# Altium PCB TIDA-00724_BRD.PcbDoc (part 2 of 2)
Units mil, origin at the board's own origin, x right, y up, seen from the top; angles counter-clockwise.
Board outline 4500 x 3350 mil, 4 copper layers (Top Layer, Signal Layer 1, Signal Layer 2, Bottom Layer), stack 61.634 mil thick; 147 components, 76 nets, 383 pads, 213 vias.
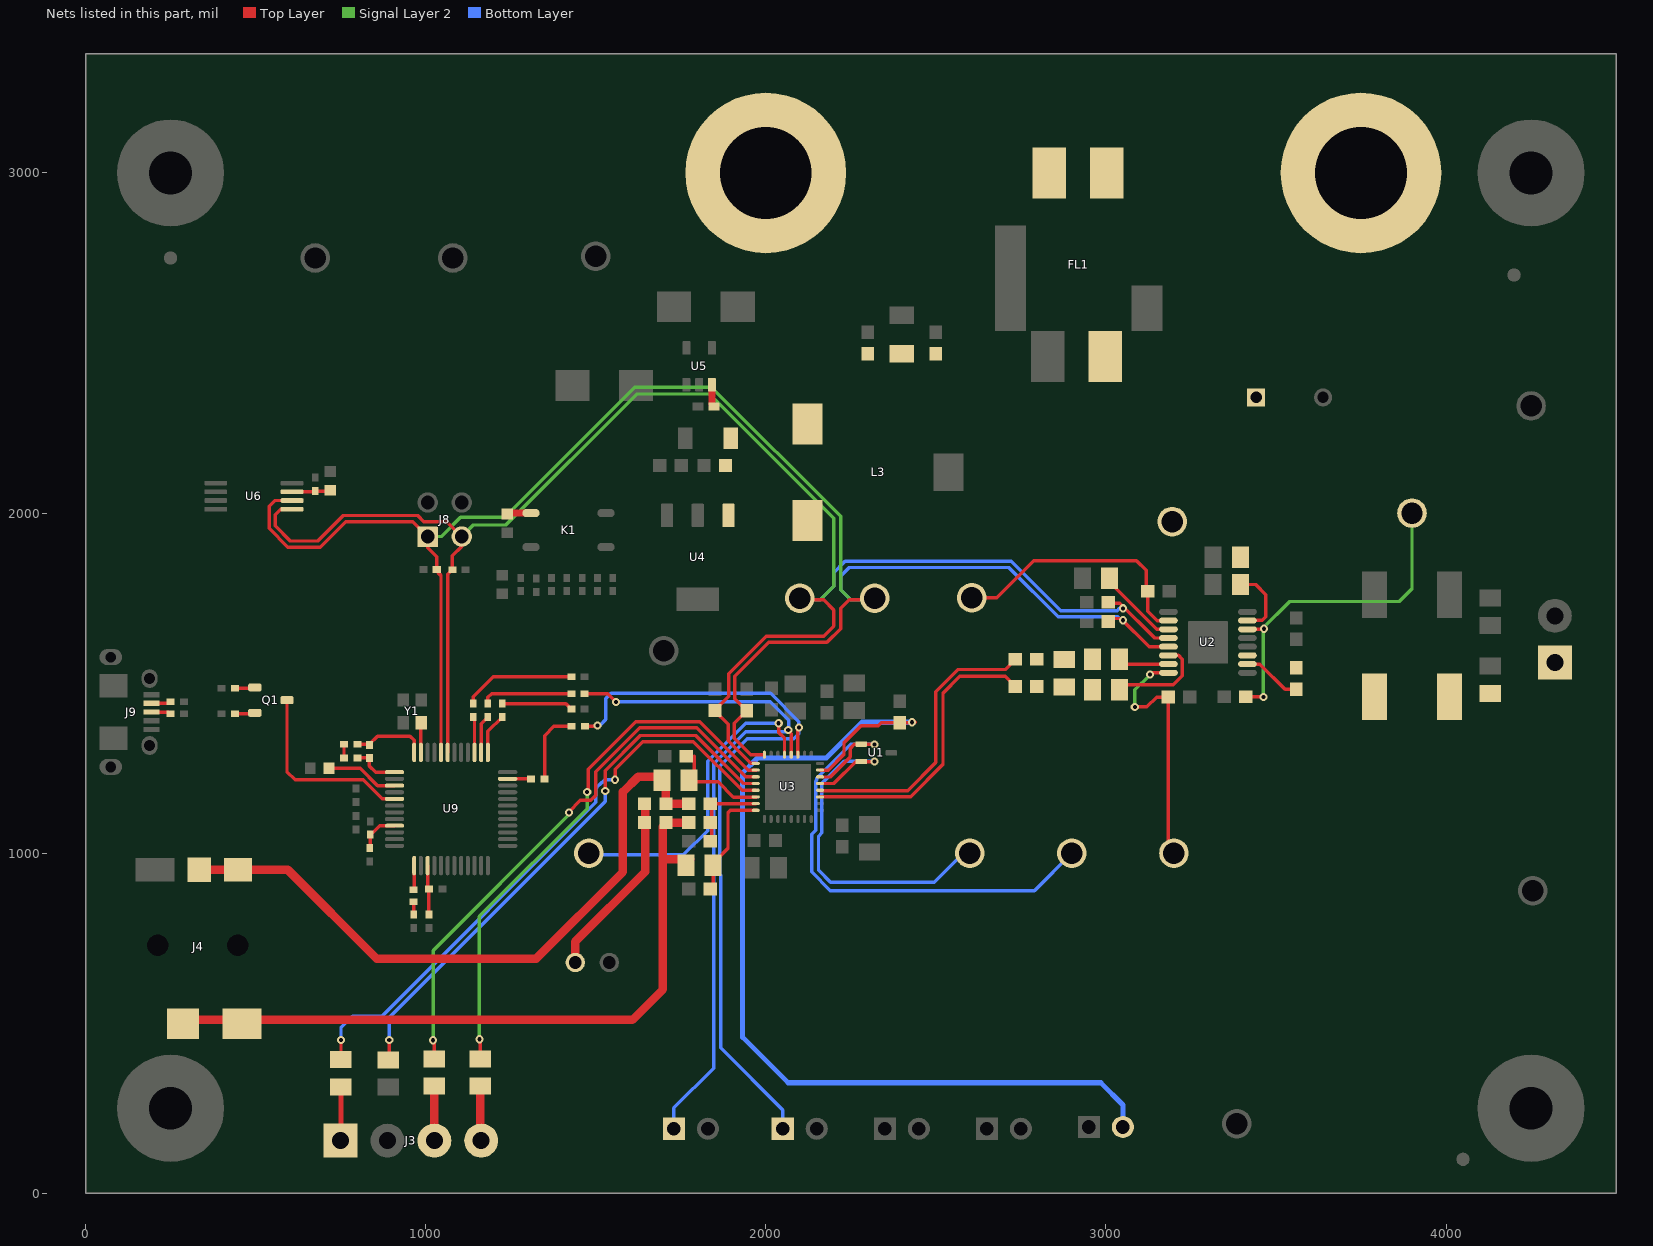
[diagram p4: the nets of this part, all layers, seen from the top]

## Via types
v1: diameter 24, hole 12, Top Layer to Bottom Layer, tented both sides, 188 vias
v2: diameter 15.75, hole 7.87, Top Layer to Bottom Layer, tented both sides, 18 vias
v3: diameter 19.68, hole 7.87, Top Layer to Bottom Layer, 5 vias
v4: diameter 20, hole 10, Top Layer to Bottom Layer, tented both sides, 2 vias

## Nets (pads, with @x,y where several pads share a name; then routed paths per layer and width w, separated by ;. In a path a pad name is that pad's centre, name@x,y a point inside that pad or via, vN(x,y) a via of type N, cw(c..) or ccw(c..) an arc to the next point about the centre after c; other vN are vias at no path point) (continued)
NetC6_2: C6.2 U3.12 | length 1664.3
  Top Layer w10: C6.2@890,383.5 893,386.5 v1(893,451) ; v1@1528,1186 1528,1242.72 1631.28,1346 1794.72,1346 1935.88,1204.84 U3.12@1970.51,1204.84
  Bottom Layer w10: v1(893,451) 893,517 1528,1152 v1(1528,1183)
NetC7_1: C7.1 J3.1 | length 166.9
  Top Layer w15: J3.1@750,155 751,156 C7.1@751,321.5
NetC7_2: C7.2 U3.13 | length 1771.4
  Top Layer w10: C7.2@751,384.5 v1(751,451) ; v1(1557,1216) 1557,1246.44 1638.68,1328.13 1787.32,1328.13 1930.29,1185.16 U3.13@1970.51,1185.16
  Bottom Layer w10: v1(751,451) 751,487 785,521 871.72,521 1500,1149.28 1500,1189 1503.13,1192.13 1503.13,1193.3 1517.7,1207.87 1518.87,1207.87 1527,1216 v1(1557,1216)
NetC8_1: C8.1 C9.2 R6.1
NetC8_2: C8.2 C12.2 R10.1
NetC9_1: C9.1 U2.6 | length 293.6
  Top Layer w10: C9.1@3040,1485 3050,1495 3197.86,1495 3224.29,1521.43 3224.29,1570.71 3213.39,1581.61 U2.6@3183.86,1581.61
NetC10_1: C10.1 L2.1 U2.11
NetC10_2: C10.2 U2.10 | length 174.3
  Top Layer w10: U2.10@3416.14,1556.02 3452.98,1556.02 3526.5,1482.5 C10.2@3560,1482.5
NetC11_1: C11.1 J1.1 L2.2
NetC12_1: C12.1 U2.7 | length 135.8
  Top Layer w10: C12.1@3048.02,1556.02 U2.7@3183.86,1556.02
NetC13_1: C13.1 U2.3 | length 243.7
  Top Layer w10: C13.1@3010,1810 3010,1798 3149.61,1658.39 U2.3@3183.86,1658.39
NetC24_1: C24.1 J3.4 | length 162.2
  Top Layer w25: C24.1@1160.59,314.41 C24.1@1160,315 1160,158.39 J3.4@1163.39,155
NetC24_2: C24.2 U3.10 | length 1600.1
  Top Layer w10: v1(1158,453) 1160,451 C24.2@1160,395 ; v1(1475,1180) 1478,1180 1478,1247 1618,1387 1806,1387 1949,1244 U3.10@1971.77,1244
  Signal Layer 2 w10: v1@1158,451 v1(1158,453) 1158,814 1475,1131 v1@1475,1178 ; v1(1475,1180) v1@1477,1180
NetC25_1: C25.1 J3.3 | length 163.4
  Top Layer w25: C25.1@1022.8,312.8 C25.1@1025,315 1025,155.59 J3.3@1025.59,155
NetC25_2: C25.2 U3.11 | length 1647.8
  Top Layer w10: v1(1022,450) 1025,447 C25.2@1025,395 ; v1(1421,1120) 1421,1121 1455.13,1155.13 1485.3,1155.13 1499.87,1169.7 1499.87,1169.87 1500,1170 1500,1240 1629,1369 1797,1369 1941,1225 U3.11@1971.77,1225
  Signal Layer 2 w10: v1@1020,449 v1@1020,450 ; v1(1022,450) 1022,714 1421,1113 v1(1421,1120)
NetC26_1: C26.1 C27.2 U3.14 | length 275.9
  Top Layer w10: 1789.5,1285 1789.5,1210 1860,1210 1905,1165 U3.14@1971.77,1165
NetC27_1: C27.1 J4.3 J4.5 R14.1 R16.2 | length 1974.5
  Top Layer w25: J4.5@333.94,951.46 J4.3@448.11,951.46 594.54,951.46 856,690 1325,690 1580,945 1580,1180 1625,1225 1685,1225 C27.1@1695,1215 1706.5,1203.5 R16.2@1706.5,1145 R14.1@1773.5,1145
NetC28_1: C28.1 J4.2 J4.4 R15.2 R17.2 | length 2090.9
  Top Layer w25: J4.4@286.69,498.7 297.99,510 1608,510 1697.63,599.63 1697.63,985 ; R15.2@1771.06,1090 1710.5,1090 1706.5,1086 1697.63,1077.13 1697.63,985 ; C28.1@1778.5,982.44 1700.19,982.44 1697.63,985
NetC28_2: C28.2 C29.1 U3.16 | length 324.8
  Top Layer w10: C29.1@1836.5,895 1845,903.5 C28.2@1845,965 ; C28.2@1841.5,982.44 1857.44,982.44 1889,1014 1889,1119 1896,1126 U3.16@1971.77,1126
NetC30_1: C30.1 R14.2 R15.1 U3.15 | length 245.6
  Top Layer w10: R14.2@1841.01,1145.79 U3.15@1970.51,1145.79 ; C30.1@1841.48,1042.46 1841.48,1157.44 R14.2@1842.27,1158.23
NetC31_1: C31.1 C32.1 C33.1 FL1.2 L3.1
NetC49_1: C49.1 R37.2 U9.1 | length 140.6
  Top Layer w10: R37.2@799.37,1280 799.69,1280.32 834.69,1280.32 834.69,1256.31 852.73,1238.27 U9.1@908.35,1238.27
NetC49_2: C49.2 C50.1 U9.48 | length 217.4
  Top Layer w10: C50.1@799.37,1320 834.37,1320 858.37,1344 911.02,1344 ; 911.05,1343.98 954.02,1343.98 966.42,1331.58 U9.48@966.42,1296.34
NetC50_2: C50.2 R37.1 | length 40
  Top Layer w10: R37.1@760,1280 C50.2@760,1320
NetC51_2: C51.2 R38.1 U9.9 | length 152
  Top Layer w10: R38.1@837,1054.32 837,1017.69 C51.2@840,1014.69 ; R38.1@839,1054.32 865.47,1080.79 U9.9@908.35,1080.79 907.44,1079.88 877.93,1079.88
NetC52_1: C52.1 R40.1 U9.15 | length 145.6
  Top Layer w10: U9.15@1005.79,963.66 1005.79,899.21 1009.69,895.32 R40.1@1009.69,819.69
NetD1_1: D1.1 R42.2 | length 37.6
  Top Layer w10: R42.2@964.69,819.69 D1.1@964.69,857.28
NetD1_2: D1.2 U9.13 | length 71.7
  Top Layer w10: D1.2@964.69,892.72 966.42,894.45 U9.13@966.42,963.66
NetFL1_1: FL1.1 J5.1
NetFL1_3: FL1.3 J6.1
NetJ2_2: J2.2 R8.1 U3.31 | length 2973.7
  Top Layer w10: U3.31@2159.49,1244.21 2183.93,1244.21 2230,1290.28 2230,1325 2280,1375 2330.71,1375 2339.2,1383.49 R8.1@2394.2,1383.49 v1@2438.49,1383.49 ; v1(2430,1385) 2435,1390 v1@2440,1385
  Bottom Layer w15: v1(2430,1385) 2282.65,1385 2177.65,1280 1975.37,1280 1932,1236.63 1932,459 2066,325 2985,325 3050,260 J2.2@3050,195
NetJ9_2: J9.2 R32.1 | length 57.9
  Top Layer w10: J9.2@194.29,1440.59 245.91,1440.59 R32.1@250.32,1445
NetJ9_3: J9.3 R34.1 | length 58.1
  Top Layer w10: J9.3@194.29,1415 245.32,1415 R34.1@250.32,1410
NetK1_1: K1.1 R19.1 | length 70.8
  Top Layer w20: R19.1@1240,1997.56 1242.44,2000 K1.1@1309.76,2000
NetMK1_2: MK1.2 R16.1 R17.1 | length 553.7
  Top Layer w25: MK1.2@1440,678.74 1440,740 1645,945 R16.1@1645,1147.5
NetQ1_1: Q1.1 R27.2 | length 59.1
  Top Layer w10: R27.2@439.69,1485 495.35,1485 Q1.1@497.76,1487.4
NetQ1_2: Q1.2 R31.1 | length 59.1
  Top Layer w10: R31.1@439.68,1410 495.16,1410 Q1.2@497.76,1412.6
NetR1_2: R1.2 TP5.1 U2.14 | length 1016.1
  Top Layer w10: R1.2@3411.5,1460 3462,1460 v1(3463,1459) ; U2.14@3416.14,1658.39 v1@3458.39,1658.39 ; v1@3456.77,1660 v1(3465,1660)
  Signal Layer 2 w10: v1@3460,1660 3540,1740 3863,1740 3900,1777 TP5.1@3900,2000 ; v1(3463,1459) v1@3463,1657
  Bottom Layer w10: v1@3460,1660 v1@3463,1657
NetR2_2: R2.2 TP6.1 U2.8 | length 746.1
  Top Layer w10: v1(3085,1430) 3120,1430 3149,1459 R2.2@3183.5,1459 3183.5,1016.5 TP6.1@3200,1000 ; v1(3130,1525) 3135.43,1530.43 U2.8@3183.86,1530.43
  Signal Layer 2 w10: v1(3085,1430) 3085,1480 v1(3130,1525)
NetR6_2: R6.2 U3.27 | length 856.4
  Top Layer w10: U3.27@2159.49,1165.47 2159.49,1165.87 2425.87,1165.87 2521,1261 2521,1470.72 2570.28,1520 2703.5,1520 R6.2@2733.5,1490
NetR10_2: R10.2 U3.28 | length 856.8
  Top Layer w10: U3.28@2159.49,1185.16 2159.49,1184.13 2417.33,1184.13 2499.87,1266.67 2499.87,1474.87 2565,1540 2703.5,1540 R10.2@2733.5,1570
NetR11_2: R11.2 TP7.1 U2.2 | length 763.3
  Top Layer w10: TP7.1@2606,1751 2679,1751 2788,1860 3090,1860 3118.5,1831.5 3118.5,1775 R11.2@3123.5,1770 3123.5,1711.5 3151.02,1683.98 U2.2@3183.86,1683.98
NetR18_2: R18.2 U5.3 | length 67
  Top Layer w20: U5.3@1841.46,2377.43 1841.46,2319.26 R18.2@1847.68,2313.03
NetR20_1: R20.1 R21.1 U6.7 | length 114.8
  Top Layer w10: U6.7@607.2,2062.48 673.11,2062.48 675,2064.37 R20.1@675,2064.69 717.87,2064.69 R21.1@720,2066.81
NetR26_1: R26.1 U9.3 | length 214
  Top Layer w10: R26.1@715.56,1250 807.28,1250 858.38,1198.9 U9.3@908.35,1198.9
NetR28_1: R28.1 U9.39 | length 105.5
  Top Layer w10: R28.1@1140,1400.32 1143.58,1396.73 U9.39@1143.58,1296.34
NetR28_2: R28.2 R29.2 | length 333.1
  Top Layer w10: R28.2@1140,1439.69 1140,1460 1199,1519 R29.2@1428.31,1519
NetR30_1: R30.1 U9.37 | length 121.4
  Top Layer w10: U9.37@1182.95,1296.34 1182.95,1358.27 R30.1@1225,1400.32
NetR30_2: R30.2 R36.2 | length 209.8
  Top Layer w10: R30.2@1225,1439.69 1412.63,1439.69 R36.2@1428.31,1424
NetR33_1: R33.1 U9.35 | length 69.5
  Top Layer w10: U9.35@1241.02,1218.58 1309.73,1218.58 R33.1@1310.32,1218
NetR33_2: R33.2 R39.2 | length 218.6
  Top Layer w10: R33.2@1349.69,1218 1349.69,1345.69 1377,1373 R39.2@1429.31,1373
NetR35_1: R35.1 U9.38 | length 112.1
  Top Layer w10: U9.38@1163.27,1296.34 1163.27,1380.58 R35.1@1183,1400.32
NetR35_2: R35.2 R41.2 | length 268.2
  Top Layer w10: R35.2@1183,1439.69 1183,1458 1194,1469 R41.2@1428.31,1469
NetTP1_1: TP1.1 U1.1 U3.30 | length 1534.2
  Top Layer w10: U3.30@2166.65,1224 2189,1224 2247.87,1282.87 2247.87,1307.87 2260.59,1320.59 U1.1@2280.71,1320.59 2319.41,1320.59 v1(2320,1320)
  Bottom Layer w10: v1(2320,1320) 2250,1320 2150,1220 2150,1215.28 2147.13,1212.4 2147.13,1067.58 2135,1055.45 2135,945 2190,890 2790,890 TP1.1@2900,1000
NetTP2_1: TP2.1 U1.2 U3.29 | length 1115.8
  Top Layer w10: U3.29@2166.65,1205 2200,1205 2264.41,1269.41 U1.2@2280.71,1269.41 2319.41,1269.41 v1(2320,1270)
  Bottom Layer w10: v1(2320,1270) 2230,1270 2165,1205 2165,1060.18 2155.13,1050.3 2155.13,950.15 2190.28,915 2495,915 2580,1000 TP2.1@2600,1000
NetTP12_1: TP12.1 U3.5 | length 959.5
  Top Layer w10: v1(2038,1382) 2038,1354.82 2055.16,1337.67 U3.5@2055.16,1289.49
  Bottom Layer w10: TP12.1@1458,995 1758,995 1829.23,1066.23 1829.23,1270.34 1940.89,1382 v1(2038,1382)
NetU9_47: U9.47 Y1.3 | length 80.3
  Top Layer w10: U9.47@986.1,1296.34 986.1,1376.38 Y1.3@986.26,1376.54
PUR: Q1.3 U9.5 | length 559.6
  Top Layer w10: Q1.3@592.24,1450 592.24,1239.76 616,1216 816,1216 872.47,1159.53 U9.5@908.35,1159.53
PVDD: C1.1 C2.1 C3.1 C34.1 C35.1 L3.2 TP8.1 U2.15 U4.1 | length 210.9
  Top Layer w10: C1.1@3395,1790 3440,1790 3470,1760 3470,1695 3459.87,1684.87 3417.04,1684.87 U2.15@3416.14,1683.98
SCL: J8.1 R4.2 R12.2 R24.1 TP3.1 U2.5 U3.8 U6.6 U9.44 | length 5346.5
  Top Layer w10: U6.6@607.2,2036.89 556.89,2036.89 540,2020 540,1955 595,1900 690,1900 765,1975 962,1975 J8.1@1006,1931 1006,1898 1032.68,1871.32 R24.1@1032.68,1834 ; R24.1@1027.68,1834 1045.16,1816.53 U9.44@1045.16,1296.34 ; U3.8@1996.1,1289.49 1955.79,1289.49 1907,1338.28 1907,1381.5 R12.2@1944,1418.5 1909,1453.5 1909,1520.72 2008.28,1620 2180,1620 2220,1660 2220,1720 2245,1745 TP3.1@2320,1745 ; R4.2@3006.5,1675 3021.5,1690 3044,1690 3126.8,1607.2 U2.5@3183.86,1607.2
  Signal Layer 2 w10: J8.1@1006,1931 1045.37,1931 1102.49,1988.13 1232.85,1988.13 1614.72,2370 1840.28,2370 2220,1990.28 2220,1775 2250,1745 TP3.1@2320,1745
  Bottom Layer w10: TP3.1@2320,1745 2250,1745 2220,1775 2220,1815 2245,1840 2714.72,1840 2859.72,1695 3035,1695 3045,1685 v1(3050,1685)
SDA: J8.3 R3.2 R13.2 R25.1 TP4.1 U2.4 U3.9 U6.5 U9.43 | length 5274.8
  Top Layer w10: U6.5@607.2,2011.3 574.29,2011.3 557.87,1994.88 557.87,1962.4 602.4,1917.87 682.6,1917.87 757.6,1992.87 977.13,1992.87 995,1975 1062,1975 J8.3@1106,1931 1106,1901.68 1078.32,1874 R25.1@1078.32,1833 1065.32,1820 1065.32,1296.81 U9.43@1064.84,1296.34 ; U3.9@1970.51,1263.9 1956.1,1263.9 1889.13,1330.87 1889.13,1379.38 1849,1419.5 1891.13,1461.63 1891.13,1528.13 2000.87,1637.87 2170,1637.87 2200,1667.87 2200,1715 2170,1745 2105,1745 TP4.1@2100,1750 ; R3.2@3006.5,1735 3041,1735 3143.2,1632.8 U2.4@3183.86,1632.8
  Signal Layer 2 w10: J8.3@1106,1931 1140,1965 1235,1965 1620,2350 1835,2350 2200,1985 2200,1785 2160,1745 2105,1745 TP4.1@2100,1740
  Bottom Layer w10: TP4.1@2100,1750 2105,1745 2160,1745 2200,1785 2200,1825 2232.87,1857.87 2722.13,1857.87 2867.13,1712.87 3032.87,1712.87 3040,1720 v1(3050,1720)
SDIN: J13.1 R41.1 U3.4 | length 2115.2
  Top Layer w10: R41.1@1467.68,1469 1535.16,1469 v1@1560.07,1444.1 ; v1@2066,1360.7 2074.84,1351.86 U3.4@2074.84,1289.49
  Bottom Layer w10: v1(1560,1445) 2013,1445 2067,1391 v1@2067,1362 ; J13.1@1730,190 1730,251 1847.11,368.11 1847.11,1262.94 1941.17,1357 v1@2066,1357
  other v1: 2066,1362
WCLK: J12.1 R39.1 U3.3 | length 2270.8
  Top Layer w10: R39.1@1468.68,1373 1498,1373 1500,1375 v1(1505,1375) ; U3.3@2094.53,1289.49 2094.53,1366.53 v1(2098,1370)
  Bottom Layer w10: v1(1505,1375) 1511.81,1375 1529.87,1393.07 1529.87,1454.87 1545,1470 2014,1470 2097,1387 2097,1351 2082.12,1336.12 1945.57,1336.12 1864.98,1255.54 1864.98,937.44 1867.13,935.29 1867.13,427.87 2050,245 J12.1@2050,190
pads on no net: FID1.1 FID2.1 FID3.1 H1.1 H2.1 H3.1 H4.1 J4.MH1 J4.MH2 J9.4 J9.M1 J9.M2 L3.3 U3.19 U3.20 U3.22 U3.23 U5.4 U9.12 U9.14 U9.17 U9.18 U9.19 U9.20 U9.22 U9.23 U9.24 U9.25 U9.26 U9.27 U9.29 U9.30 U9.31 U9.32 U9.34 U9.36 U9.40 U9.41 U9.42 U9.46

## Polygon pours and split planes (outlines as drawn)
GND on Signal Layer 1 "Signal Layer 1-No Net" (solid, remove dead copper, pour order 5): 10,3340 10,10 4490,10 4490,3340
GND on Top Layer "Top Layer-No Net" (solid, remove dead copper, pour order 8): 10,3340 10,10 4490,10 4490,3340
GND on Bottom Layer "Top Layer-No Net" (solid, remove dead copper, pour order 7): 9.47,3340 9.47,10 4489.47,10 4489.47,3340
GND on Signal Layer 2 "Top Layer-No Net" (solid, remove dead copper, pour order 6): 10,3340 10,10 4490,10 4490,3340

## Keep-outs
Keep-Out Layer:
  the board outline again, w5
  text ".Layer_Name" at 577,-858.49 h60

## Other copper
Top Layer:
  region net NetC8_1: 2802.6,1445 2995,1445 2995,1520 2775,1520 2775,1472.6
  region net NetC8_2: 2775,1590 2775,1535 2995,1535 2995,1605 2790,1605
  pour cut-out: 2735,1591 2745,1591 2745,1640 2735,1640
  pour cut-out: 2745,1460 2755,1460 2755,1440 2745,1440
  pour cut-out: 2670,1605 2705,1640 2740,1640 2740,1630 2705,1630 2670,1595
  region net GND: 2193.2,1126 2451,1126 2565,1240 2565,1420 2595,1450 2705,1450 2705,1490 2701,1494 2568,1494 2535,1461 2535,1255 2433,1153 2208,1153 2193.2,1138.2
  region net GND: 2221,1206 2221,1197 2412,1197 2487,1272 2487,1492 2550,1555 2685,1555 2700,1570 2700,1595 2710,1605 2735,1605 2735,1630 2705,1630 2670,1595 2530,1595 2455,1520 2455,1285 2394,1224 2239,1224
  region net 1.8V: 2161.3,1435 2161.3,1388.7 2175,1375 2175,1320 2147,1292 2147,1258 2178,1258 2215,1295 2215,1335 2271,1391 2290,1391 2290,1450 2215,1450 2200,1435
  region net 3.3V: 2129,1115 2150,1115 2150,1132 2183,1132 2183,1062 2195,1050 2350,1050 2350,950 2179,950 2129,1000
  region net NetC5_1: 3390,1610.12 3390,1604 3395,1599 3840,1599 3840,1845 3745,1845 3745,1685 3720,1660 3550,1660 3505,1615 3394.87,1615
  region net NetC10_1: 3398.48,1590 3840,1590 3840,1380 3740,1380 3740,1493 3712,1521 3542,1521 3490,1573 3398.52,1573 3390,1581.52
  region net NetC11_1: 4390,1620 4290,1620 4170,1500 4080,1500 4050,1530 3940,1530 3940,1360 4390,1360
  region net NetC4_2: 4390,1640 4390,1870 3940,1870 3940,1690 4050,1690 4080,1720 4200,1720 4280,1640
  region net NetFL1_1: 4060,3300 3130,3300 2940,3110 2940,2900 3150,2900 3310,2740 4060,2740
  region net NetFL1_3: 1700,3300 2730,3300 2900,3130 2900,2900 2650,2900 2490,2740 1700,2740
  region net PVDD: 1860,1960 1905,1915 3360,1915 3360,1750 3430,1750 3475,1795 3475,2375 3405,2375 3405,2070 3375,2040 1955,2040 1920,2075 1920,2255 1860,2255
  region net NetC31_1: 2940,2550 2940,2390 2910,2360 2700,2360 2560,2500 2150,2500 2040,2390 2040,2204.41 2089.41,2155 2350,2155 2430,2235 2970,2235 3060,2325 3060,2550
  region net 3.3V: 1780,2350 1780,2408.37 1758.37,2430 1570,2430 1550,2410 1550,2115 1500,2065 1500,1980 1535,1945 1725,1945 1750,1970 1750,2055 1720,2085 1720,2290
  region net 1.8V: 1670.51,2690 1670.51,2499.49 1706.97,2463.03 1800,2463.03 1800,2690
  pour cut-out: 2239,1235 2239,1225 2395,1225 2455,1285 2455,1520 2530,1595 2670,1595 2670,1605 2525,1605 2445,1525 2445,1285 2395,1235
  pour cut-out: 2186,1126 2186,1118 2453,1118 2575,1240 2575,1415 2600,1440 2745,1440 2745,1450 2595,1450 2565,1420 2565,1240 2451,1126
  region net 3.3V-USB: 1490,1925 1420,1855 1222.09,1855 1195,1827.91 1195,1795 1580,1795 1580,1925
  region net GND: 330,2124.69 465,2124.69 465,1969.69 330,1969.69
  region net GND: 1206.92,1086 1285,1086 1285,1075 1206.92,1075
  region net GND: 1020.26,929.56 1020.26,1007.64 1031.26,1007.64 1031.26,929.56
  region net GND: 1020.26,1262.23 1020.26,1340.32 1031.26,1340.32 1031.26,1262.23
  text ".Layer_Name" at 577,-858.49 h60
Signal Layer 1:
  text ".Layer_Name" at 577,-858.49 h60
Signal Layer 2:
  region net 3.3V: 1745,2305 1635,2305 1635,1165 1885,915 2350,915 2350,1065 1899.98,1065 1810,1154.98 1810,1385 1827,1402 2414.9,1402 2445,1432.1 2445,1515 1915,1515 1745,1685
  text ".Layer_Name" at 577,-858.49 h60
Bottom Layer:
  text ".Layer_Name" at 577,-858.49 h60

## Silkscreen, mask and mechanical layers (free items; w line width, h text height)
Top Overlay:
  text ".PRJ_Number" at 3235,500 h100
  text "A" at 3835,500 h100
  text ".Layer_Name" at 577,-858.49 h60
Bottom Overlay:
  text ".Layer_Name" at 577,-858.49 h60
Top Paste:
  text ".Layer_Name" at 577,-858.49 h60
Bottom Paste:
  text ".Layer_Name" at 577,-858.49 h60
Top Solder:
  text ".Layer_Name" at 577,-858.49 h60
  text ".Layer_Name" at 577,-858.49 h60
Bottom Solder:
  text ".Layer_Name" at 577,-858.49 h60
Drill Guide:
  text ".Layer_Name" at 577,-858.49 h60
M1 Board Outline:
  the board outline again, w10
  text ".Layer_Name" at 577,-858.49 h60
M2 Board Dimensions:
  rectangle: 125,-400 500,-275
  rectangle: 0,-275 125,-150
  lines w7: 0,-275 1000,-275 ; 125,-400 125,-150 ; 250,-400 250,-150 ; 500,-400 500,-150 ; 750,-400 750,-150 ; 0,-400 0,-150 1000,-150 1000,-400 0,-400
  text ".Layer_Name" at 577,-858.49 h60
M3 3D STEP Top:
  text ".Layer_Name" at 577,-858.49 h60
M4 3D STEP Bottom:
  text ".Layer_Name" at 577,-858.49 h60
M5 Assembly Top:
  lines w10: -292,-930.17 6308,-930.17 ; -292,-726.83 6310,-726.83 ; -292,-523.5 -292,-1133.5 3713,-1133.5 6310,-1133.5 6310,-523.5 -291.5,-523.5 -291.5,-1133.5 1284,-1133.5 ; 2173,-1133.5 2173,-523.5 ; 3440,-726.83 3440,-523.5 ; 4280,-726.83 4280,-523.5 ; 4902,-1140 4902,-937.17
  text "COMPONENTS MARKED 'DNP' SHOULD NOT BE POPULATED." at 1153.5,-318.5 h60
  text "ASSEMBLY VARIANT:" at 1153,-434 h60
  text ".VariantName" at 2189,-434 h60
  text "PCB VIEWED FROM TOP SIDE" at -228.5,-655.67 h60
  text "BOARD #:" at 2248,-655.67 h60
  text ".PRJ_Number" at 2793.5,-655.67 h60
  text "REV:" at 3638,-655.67 h60
  text ".PCB_Rev" at 3929.5,-655.67 h60
  text "SVN REV:" at 4476,-655.67 h60
  text ".VersionControl_RevNumber" at 4982,-655.67 h60
  text "TID #:" at 2248,-859 h60
  text ".TID" at 2793.5,-859 h60
  text "PLOT NAME =" at -228.5,-1064.34 h60
  text ".plot_File_Name" at 577,-1064.34 h60
  text "GENERATED    :" at 2250,-1064.34 h60
  text ".Print_Date" at 3119.5,-1064.34 h60
  text ".Print_Time" at 3848.5,-1064.34 h60
  text "TEXAS INSTRUMENTS" at 5113,-1064.34 h60
M6 Assembly Bottom:
  lines w10: -292.5,-727.33 6309.5,-727.33 ; -290.5,-930.67 6309.5,-930.67 ; 1115.5,-1140.5 1115.5,-937.67 ; 1737.5,-727.33 1737.5,-524 ; 2577.5,-727.33 2577.5,-524 ; 3844.5,-1134 3844.5,-524 ; 4733.5,-1134 6309,-1134 6309,-524 -292.5,-524 -292.5,-1134 2304.5,-1134 6309.5,-1134 6309.5,-524
  text "COMPONENTS MARKED 'DNP' SHOULD NOT BE POPULATED." at 6102,-318 h60
  text ".VariantName" at 5058,-434 h60
  text "ASSEMBLY VARIANT:" at 6097,-434 h60
  text ".VersionControl_RevNumber" at 1035.5,-656.17 h60
  text "SVN REV:" at 1541.5,-656.17 h60
  text ".PCB_Rev" at 2088,-656.17 h60
  text "REV:" at 2379.5,-656.17 h60
  text ".PRJ_Number" at 3224,-656.17 h60
  text "BOARD #:" at 3769.5,-656.17 h60
  text "PCB VIEWED FROM BOTTOM SIDE" at 6246,-656.17 h60
  text ".TID" at 3224,-859.5 h60
  text "TID #:" at 3769.5,-859.5 h60
  text "TEXAS INSTRUMENTS" at 904.5,-1064.84 h60
  text ".Print_Time" at 2169,-1064.84 h60
  text ".Print_Date" at 2898,-1064.84 h60
  text "GENERATED    :" at 3767.5,-1064.84 h60
  text ".plot_File_Name" at 5440.5,-1064.84 h60
  text "PLOT NAME =" at 6246,-1064.84 h60
M9 Title Sheet:
  drawing of 57 lines, arcs and shapes, not listed
  text "1" at 739.84,8036.5 h70
  text "2" at 3235.5,8036.5 h70
  text "3" at 5724.84,8036.5 h70
  text "4" at 8231.51,8036.5 h70
  text "5" at 10730.5,8036.5 h70
  text "6" at 13235.5,8036.5 h70
  text "A" at -416.5,6893.5 h70
  text "A" at 14383.5,6893.5 h70
  text "B" at -416.5,4513.5 h70
  text "B" at 14383.5,4513.5 h70
  text "C" at -416.5,2138.5 h70
  text "C" at 14383.5,2138.5 h70
  text "PROJECT TITLE:" at 11343.5,277.5 h45
  text ".PRJ_Title" at 11393.5,144.17 h70
  text "DESIGNED FOR:" at 11343.5,-23.5 h45
  text ".PRJ_Customer" at 11393.5,-163.5 h70
  text "D" at -416.5,-231.5 h70
  text "D" at 14383.5,-231.5 h70
  text "FILE NAME:" at 11343.5,-323.5 h45
  text ".PCB_File_Name_No_Path" at 11393.5,-443.5 h70
  text "Texas Instruments (TI) and/or its licensors do not warrant the accuracy or completeness of this specification" at 6374,-605.34 h45
  text "ENGINEER:" at 11343.5,-613.5 h45
  text "LAYOUT BY:" at 12848.5,-613.5 h45
  text "or any information contained therein. TI and/or its licensors do not warrant that this design will meet" at 6329.01,-718 h45
  text ".PRJ_Engineer" at 11393.5,-768.49 h70
  text ".PCB_Layout" at 12899,-768.49 h70
  text "the specifications, will be suitable for your application or fit for any particular purpose, or will operate in" at 6329.01,-830.67 h45
  text ".Layer_Name" at 577,-858.49 h60
  text "ALTIUM DESIGNER VERSION:" at 12848.5,-923.5 h45
  text "an implementation. TI and/or its licensors do not warrant that the design is production worthy. You should" at 6329.01,-943.33 h45
  text "completely validate and test your design implementation to confirm the system functionality for your application." at 6374,-1056 h45
  text ".print_Scale" at 11393.5,-1056.83 h70
  text ".Application_BuildNumber" at 12899,-1056.83 h70
  text "1" at 739.84,-1263.5 h70
  text "2" at 3235.5,-1263.5 h70
  text "3" at 5724.84,-1263.5 h70
  text "4" at 8231.51,-1263.5 h70
  text "5" at 10730.5,-1263.5 h70
  text "6" at 13235.5,-1263.5 h70
M10 Fab Notes:
  drawing of 185 lines, arcs and shapes, not listed
  text "DESIGN INFORMATION" at 12381.02,5910 h60
  text "MIN. TRACK WIDTH:" at 11736.46,5730 h60
  text "8" at 12832.7,5730 h60
  text "MIL" at 12987.46,5730 h60
  text "MIN. CLEARANCE:" at 11736.46,5598 h60
  text "0.2" at 12772.7,5598 h60
  text "mm" at 12987.46,5598 h60
  text "MIN. VIA PAD SIZE:" at 11736.46,5466 h60
  text "24" at 12802.71,5466 h60
  text "MIL" at 12987.46,5466 h60
  text "0.05mm (2MIL)" at 12431.46,5324.29 h60
  text "MINIMUM ANNULAR RING" at 11407.23,5320 h60
  text "EXTERNAL" at 13139.46,5320 h60
  text "PER" at 11607.23,5202 h60
  text "IPC-D-275 CLASS 2 LEVEL C" at 11827.23,5202 h60
  text "MIL, HOLES" at 13315.46,5089.71 h60
  text "+/-" at 12923,5089 h60
  text "+/-" at 13777,5089 h60
  text "REGISTRATION TOLERANCES:" at 11407.23,5084 h60
  text "METAL" at 12607,5084 h60
  text "5" at 13183.2,5084 h60
  text "3" at 14016.2,5084 h60
  text "MIL" at 14132.46,5084 h60
  text "MATERIAL:" at 11332.46,4874.54 h60
  text "FR-4 High Tg" at 12318.9,4734.21 h60
  text "FR-408" at 11753.46,4725.64 h60
  text "X" at 12165.46,4725.64 h60
  text "OTHER" at 13241.46,4725.64 h60
  text "62 MIL (1.6mm) +/-10%" at 12073.56,4562.92 h60
  text "THICKNESS:" at 11407.23,4558.64 h60
  text "X" at 11945.4,4558.64 h60
  text "OTHER" at 13358.46,4558.64 h60
  text "TOLERANCE:" at 11407.23,4400.64 h60
  text "X" at 12246.53,4400.64 h60
  text "ANSI IPC-6012 TYPE 3 CLASS 2" at 12433.48,4400.64 h60
  text "OTHER +/-" at 12433.46,4244.64 h60
  text "BOW & TWIST:" at 11407.23,4087.64 h60
  text "X" at 12246.53,4087.64 h60
  text "ANSI IPC-6012 TYPE 3 CLASS 2" at 12433.48,4087.64 h60
  text "OTHER +/-" at 12433.46,3929.13 h60
  text "DRILLING:" at 11332.46,3790.64 h60
  text "REFERENCE:" at 11407.23,3673.64 h60
  text "X" at 12055.46,3673.64 h60
  text "AS SHOWN" at 12242.46,3673.64 h60
  text "X" at 12956.46,3673.64 h60
  text "NC_DRILL FILES" at 13093.46,3673.64 h60
  text "PTH MIN COPPER THICKNESS:" at 11407.23,3515.64 h60
  text "X" at 12757.46,3515.64 h60
  text "1MIL" at 12894.46,3515.64 h60
  text "OTHER" at 13391.46,3515.64 h60
  text "BOARD FINISH:" at 11332.46,3356.64 h60
  text "SILKSCREEN:" at 11487.68,3238.64 h60
  text "X" at 12436.46,3238.64 h60
  text "TOP" at 12562.46,3238.64 h60
  text "X" at 12946.46,3238.64 h60
  text "BOTTOM" at 13073.46,3238.64 h60
  text "SILKSCREEN COLOR:" at 11487.68,3071.64 h60
  text "X" at 12435.42,3071.64 h60
  text "WHITE" at 12562.46,3071.64 h60
  text "OTHER" at 13073.46,3071.64 h60
  text "SOLDER RESIST COLOR:" at 11487.68,2901.64 h60
  text "X" at 12055.42,2742.44 h60
  text "GREEN" at 12182.46,2742.44 h60
  text "BLUE" at 12773.46,2742.44 h60
  text "OTHER" at 13311.46,2742.44 h60
  text "IMMERSION GOLD (ENIG)" at 12393.46,2553.92 h60
  text "ENEPIG" at 13731,2550.64 h60
  text "SURFACE FINISH:" at 11332.46,2549.64 h60
  text "X" at 12206.51,2549.64 h60
  text "IMM. TIN/SILVER OR EQUIV" at 11662,2392.64 h60
  text "OTHER" at 13093.46,2392.64 h60
  text "ARRAY/PANEL:" at 11332.46,2213.64 h60
  text "CUT AND TRIM PER MECH LAYER 1" at 12393.46,2209.35 h60
  text "N.C. ROUTE" at 12393.46,2057.64 h60
  text "X" at 13072.46,2057.64 h60
  text "V. SCORE" at 13259.46,2057.64 h60
  text "CERTIFICATION:" at 11332.46,1920.64 h60
  text "MATERIALS AND WORKMANSHIP FOR ALL PCBS" at 12057.46,1920.64 h60
  text "TO MEET OR EXCEED THE REQUIREMENTS OF:" at 12057.46,1822.64 h60
  text "X" at 11683.96,1686.13 h60
  text "ANSI IPC-A-600F CLASS ->" at 11822.96,1686.13 h60
  text "X" at 13462.02,1686.13 h60
  text "2" at 13580.96,1686.14 h60
  text "1" at 13265.96,1684.64 h60
  text "3" at 13934.96,1684.64 h60
  text "X" at 11686.02,1526.64 h60
  text "UL 94V-0" at 11822.96,1526.64 h60
  text "X" at 12498.02,1526.64 h60
  text "RoHS" at 12634.96,1526.64 h60
  text "OTHER" at 13279.36,1526.64 h60
  text "PER ORDER" at 13676.42,1526.64 h60
  text "ADDITIONAL REQUIREMENTS:" at 11332.46,1385.64 h60
  text "MICROSECTION:" at 11407.23,1270.64 h60
  text "YES" at 12312.96,1270.64 h60
  text "REQUIRED" at 13174.46,1114.49 h60
  text "BARE BOARD ELEC. TEST:" at 11407.23,1111.64 h60
  text "NONE" at 12712.96,1111.64 h60
  text "X" at 13047.46,1111.64 h60
  text "PER ORDER" at 13766.46,1111.64 h60
  text "MANUFACTURER'S UL:" at 11407.23,954.64 h60
  text "RAIL" at 12572.96,950.35 h60
  text "METAL" at 13064.77,950.35 h60
  text "X" at 13440,950 h60
  text "SILK" at 13576.46,950.35 h60
  text ".Layer_Name" at 577,-858.49 h60
M11 Gerber Information:
  lines w10: -292,-930.17 6308,-930.17 ; -292,-726.83 6310,-726.83 ; -292,-523.5 -292,-1133.5 3713,-1133.5 6310,-1133.5 6310,-523.5 -291.5,-523.5 -291.5,-1133.5 1284,-1133.5 ; 2173,-1133.5 2173,-523.5 ; 3440,-726.83 3440,-523.5 ; 4280,-726.83 4280,-523.5 ; 4902,-1140 4902,-937.17
  text "ALL ARTWORK VIEWED FROM TOP SIDE" at -228.5,-655.67 h60
  text "BOARD #:" at 2248,-655.67 h60
  text ".PRJ_Number" at 2793.5,-655.67 h60
  text "REV:" at 3638,-655.67 h60
  text ".PCB_Rev" at 3929.5,-655.67 h60
  text "SVN REV:" at 4476,-655.67 h60
  text ".VersionControl_RevNumber" at 4982,-655.67 h60
  text "LAYER NAME =" at -228.5,-858.49 h60
  text "TID #:" at 2248,-859 h60
  text ".TID" at 2793.5,-859 h60
  text "PLOT NAME =" at -228.5,-1064.34 h60
  text ".plot_File_Name" at 577,-1064.34 h60
  text "GENERATED    :" at 2250,-1064.34 h60
  text ".Print_Date" at 3119.5,-1064.34 h60
  text ".Print_Time" at 3848.5,-1064.34 h60
  text "TEXAS INSTRUMENTS" at 5113,-1064.34 h60
M12 Stackup:
  drawing of 295 lines, arcs and shapes, not listed
  text "Layer" at 9720,7740 h60
  text "Name" at 10129.91,7740 h60
  text "Material" at 11069.65,7740 h60
  text "Thickness" at 11929.42,7740 h60
  text "Constant" at 12579.26,7740 h60
  text "Board Layer Stack" at 13149.12,7740 h60
  text "1" at 9720,7620 h60
  text "Top Overlay" at 10129.91,7620 h60
  text "2" at 9720,7500 h60
  text "Top Solder" at 10129.91,7500 h60
  text "Solder Resist" at 11069.65,7500 h60
  text "0.40mil" at 11929.42,7500 h60
  text "3.5" at 12579.26,7500 h60
  text "3" at 9720,7380 h60
  text "Top Layer" at 10129.91,7380 h60
  text "Copper" at 11069.65,7380 h60
  text "1.40mil" at 11929.42,7380 h60
  text "4" at 9720,7260 h60
  text "Dielectric1" at 10129.91,7260 h60
  text "FR-4" at 11069.65,7260 h60
  text "13.00mil" at 11929.42,7260 h60
  text "4.2" at 12579.26,7260 h60
  text "5" at 9720,7140 h60
  text "Signal Layer 1" at 10129.91,7140 h60
  text "Copper" at 11069.65,7140 h60
  text "1.42mil" at 11929.42,7140 h60
  text "6" at 9720,7020 h60
  text "Dielectric 3" at 10129.91,7020 h60
  text "FR-4" at 11069.65,7020 h60
  text "30.00mil" at 11929.42,7020 h60
  text "4.2" at 12579.26,7020 h60
  text "7" at 9720,6900 h60
  text "Signal Layer 2" at 10129.91,6900 h60
  text "Copper" at 11069.65,6900 h60
  text "1.42mil" at 11929.42,6900 h60
  text "8" at 9720,6780 h60
  text "Dielectric 2" at 10129.91,6780 h60
  text "FR-4" at 11069.65,6780 h60
  text "13.00mil" at 11929.42,6780 h60
  text "4.2" at 12579.26,6780 h60
  text "9" at 9720,6660 h60
  text "Bottom Layer" at 10129.91,6660 h60
  text "Copper" at 11069.65,6660 h60
  text "1.40mil" at 11929.42,6660 h60
  text "10" at 9720,6540 h60
  text "Bottom Solder" at 10129.91,6540 h60
  text "Solder Resist" at 11069.65,6540 h60
  text "0.40mil" at 11929.42,6540 h60
  text "3.5" at 12579.26,6540 h60
  text "11" at 9720,6420 h60
  text "Bottom Overlay" at 10129.91,6420 h60
  text ".Layer_Name" at 577,-858.49 h60
M13 Component Bodies Top:
  text ".Layer_Name" at 577,-858.49 h60
M14 Component Bodies Bottom:
  text ".Layer_Name" at 577,-858.49 h60
M15 Courtyards Top:
  text ".Layer_Name" at 577,-858.49 h60
M16 Courtyards Bottom:
  text ".Layer_Name" at 577,-858.49 h60
Drill Drawing:
  circle w1: c5602.8,2441.37 r24.91
  circle w1: c5602.8,946.78 r14.95
  circle w1: c5602.8,946.78 r24.91
  lines w1: 5577.89,822.24 5627.71,822.24 5602.8,772.42 5577.89,822.24 ; 5577.89,1071.33 5627.71,1071.33 5627.71,1121.15 5577.89,1121.15 5577.89,1071.33 ; 5577.89,1220.79 5627.71,1220.79 5627.71,1270.61 5577.89,1270.61 5577.89,1220.79 ; 5577.89,1395.16 5602.8,1370.25 5627.71,1395.16 5602.8,1420.07 5577.89,1395.16 ; 5577.89,1532.16 5590.35,1532.16 5590.35,1519.71 5615.26,1519.71 5615.26,1532.16 5627.71,1532.16 5627.71,1557.07 5615.26,1557.07 5615.26,1569.53 5590.35,1569.53 5590.35,1557.07 5577.89,1557.07 5577.89,1532.16 ; 5577.89,1669.17 5602.8,1681.62 5627.71,1669.17 5615.26,1694.08 5627.71,1718.99 5602.8,1706.53 5577.89,1718.99 5590.35,1694.08 5577.89,1669.17 ; 5577.89,1831.08 5590.35,1831.08 5602.8,1818.63 5615.26,1831.08 5627.71,1831.08 5615.26,1843.54 5627.71,1855.99 5615.26,1855.99 5602.8,1868.45 5590.35,1855.99 5577.89,1855.99 5590.35,1843.54 5577.89,1831.08 ; 5577.89,2017.91 5627.71,2017.91 5602.8,1968.09 5577.89,2017.91 ; 5577.89,2117.54 5577.89,2130 5590.35,2142.45 5577.89,2154.91 5577.89,2167.36 5590.35,2167.36 5602.8,2154.91 5615.26,2167.36 5627.71,2167.36 5627.71,2154.91 5615.26,2142.45 5627.71,2130 5627.71,2117.54 5615.26,2117.54 5602.8,2130 5590.35,2117.54 5577.89,2117.54 ; 5577.89,2279.46 5590.35,2279.46 5590.35,2267 5615.26,2267 5615.26,2279.46 5627.71,2279.46 5627.71,2304.37 5615.26,2304.37 5615.26,2316.82 5590.35,2316.82 5590.35,2304.37 5577.89,2304.37 5577.89,2279.46 ; 5577.89,2565.92 5577.89,2578.38 5590.35,2590.83 5577.89,2603.28 5577.89,2615.74 5590.35,2615.74 5602.8,2603.28 5615.26,2615.74 5627.71,2615.74 5627.71,2603.28 5615.26,2590.83 5627.71,2578.38 5627.71,2565.92 5615.26,2565.92 5602.8,2578.38 5590.35,2565.92 5577.89,2565.92 ; 5587.85,812.27 5617.75,812.27 5602.8,782.38 5587.85,812.27 ; 5587.85,1081.3 5617.75,1081.3 5617.75,1111.19 5587.85,1111.19 5587.85,1081.3 ; 5587.85,2127.51 5587.85,2134.98 5595.33,2142.45 5587.85,2149.93 5587.85,2157.4 5595.33,2157.4 5602.8,2149.93 5610.27,2157.4 5617.75,2157.4 5617.75,2149.93 5610.27,2142.45 5617.75,2134.98 5617.75,2127.51 5610.27,2127.51 5602.8,2134.98 5595.33,2127.51 5587.85,2127.51 ; 5587.85,2284.44 5595.33,2284.44 5595.33,2276.97 5610.27,2276.97 5610.27,2284.44 5617.75,2284.44 5617.75,2299.39 5610.27,2299.39 5610.27,2306.86 5595.33,2306.86 5595.33,2299.39 5587.85,2299.39 5587.85,2284.44
  lines w12: 5510,727.58 7629.4,727.58 ; 5510,2670.54 7629.4,2670.54 ; 5880.67,578.12 5880.67,2820 ; 6237.78,578.12 6237.78,2820 ; 6899.79,578.12 6899.79,2820 ; 7184.14,578.12 7184.14,2820 ; 5510,578.12 7629.4,578.12 7629.4,2820 5510,2820 5510,578.12
  text "Symbol" at 5599.68,2715.38 h72
  text "Quantity" at 5925.51,2715.38 h72
  text "Finished Hole Size" at 6282.62,2715.38 h72
  text "Plated" at 6944.62,2715.38 h72
  text "Hole Type" at 7228.98,2715.38 h72
  text "2" at 5925.51,2565.92 h60
  text "62.99mil (1.600mm)" at 6282.62,2565.92 h60
  text "NPTH" at 6944.62,2565.92 h60
  text "Round" at 7228.98,2565.92 h60
  text "23" at 5925.51,2416.46 h60
  text "7.87mil (0.200mm)" at 6282.62,2416.46 h60
  text "PTH" at 6944.62,2416.46 h60
  text "Round" at 7228.98,2416.46 h60
  text "2" at 5925.51,2267 h60
  text "10.00mil (0.254mm)" at 6282.62,2267 h60
  text "PTH" at 6944.62,2267 h60
  text "Round" at 7228.98,2267 h60
  text "188" at 5925.51,2117.54 h60
  text "12.00mil (0.305mm)" at 6282.62,2117.54 h60
  text "PTH" at 6944.62,2117.54 h60
  text "Round" at 7228.98,2117.54 h60
  text "2" at 5925.51,1968.09 h60
  text "33.46mil (0.850mm)" at 6282.62,1968.09 h60
  text "PTH" at 6944.62,1968.09 h60
  text "Round" at 7228.98,1968.09 h60
  text "2" at 5925.51,1818.63 h60
  text "37.40mil (0.950mm)" at 6282.62,1818.63 h60
  text "PTH" at 6944.62,1818.63 h60
  text "Round" at 7228.98,1818.63 h60
  text "14" at 5925.51,1669.17 h60
  text "40.00mil (1.016mm)" at 6282.62,1669.17 h60
  text "PTH" at 6944.62,1669.17 h60
  text "Round" at 7228.98,1669.17 h60
  text "6" at 5925.51,1519.71 h60
  text "50.00mil (1.270mm)" at 6282.62,1519.71 h60
  text "PTH" at 6944.62,1519.71 h60
  text "Round" at 7228.98,1519.71 h60
  text "16" at 5925.51,1370.25 h60
  text "63.00mil (1.600mm)" at 6282.62,1370.25 h60
  text "PTH" at 6944.62,1370.25 h60
  text "Round" at 7228.98,1370.25 h60
  text "4" at 5925.51,1220.79 h60
  text "125.98mil (3.200mm)" at 6282.62,1220.79 h60
  text "PTH" at 6944.62,1220.79 h60
  text "Round" at 7228.98,1220.79 h60
  text "2" at 5925.51,1071.33 h60
  text "270.00mil (6.858mm)" at 6282.62,1071.33 h60
  text "PTH" at 6944.62,1071.33 h60
  text "Round" at 7228.98,1071.33 h60
  text "2" at 5925.51,921.87 h60
  text "31.50mil (0.800mm)" at 6282.62,921.87 h60
  text "PTH" at 6944.62,921.87 h60
  text "Slot" at 7228.98,921.87 h60
  text "2" at 5925.51,772.42 h60
  text "31.50mil (0.800mm)" at 6282.62,772.42 h60
  text "PTH" at 6944.62,772.42 h60
  text "Slot" at 7228.98,772.42 h60
  text "265 Total" at 5925.51,622.96 h60
  text ".Layer_Name" at 577,-858.49 h60

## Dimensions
0,0 to 0,3350 on M2 Board Dimensions
0,0 to 4500,0 on M2 Board Dimensions
0,-400 to 1000,-400 on M2 Board Dimensions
